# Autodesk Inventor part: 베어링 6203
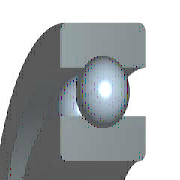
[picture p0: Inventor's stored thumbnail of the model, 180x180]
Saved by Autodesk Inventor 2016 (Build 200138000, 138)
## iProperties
IsCustomPart: 1
Created: 2015-09
Part Number: 베어링 6203
Material: 강철, 연강
Description: 깊은 그루브 볼 베어링
Document SubType Name: Modeling
Standard: KS B 2023
Standards Organization: KS
Language: ko-KR
Size Designation: 6203 - 17 x 40 x 12
Categories: <MemberInstance><Categories><Category DisplayName="샤프트 부품" InternalName="7f7aeb1f-a693-4053-b835-cee3144e0d98" Mnemonic="SHFT"><Category DisplayName="베어링" Inter
Density: 7.86 g/cm^3
Mass: 64.9809 g
Surface Area: 64.3582 cm^2
Volume: 8.26729 cm^3
Appearance: 노란색
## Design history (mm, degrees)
sketch "스케치" dims "d0" = 5.98 (= -0.26 x WD + 0.26 x BD)
  geometry: L1 (3.01, 14.25)-(8.99, 14.25); L2 (6, 14.25)-(6, 11.26); L3 (6, 14.25)-(6, 17.24); L4 (3.778, 12.249)-(0, 12.249); L5 (0, 8.5)-(12, 8.5); L6 (3.778, 16.251)-(0, 16.251); L7 (0, 20)-(12, 20); L8 (12, 8.5)-(12, 12.249); L9 (8.222, 12.249)-(12, 12.249); L10 (8.222, 16.251)-(12, 16.251); L11 (12, 20)-(12, 16.251); L12 (-1.4, 0)-(8.4, 0) reference; L13 (0, -0.3)-(0, 5.3) reference
  constraints: 22 end point, 4 point on line, 2 collinear, 2 perpendicular, 2 symmetric about line, 1 midpoint, 1 parallel, 14 other
  dimensions: "d9" = 17 diameter of L5 L12 (= WD); "d11" = 40 diameter of L7 L12 (= BD); "d12" = 12 distance between parallel lines of L8 L13 (= KB); "d13" = 24.498 diameter of L9 L12 (= 0.326 x BD + 0.674 x WD)
revolve "본체" stored, may be unused: angle "d6" = 90 deg
revolve "볼" stored, may be unused: angle "d7" = 90 deg
pattern_circular "IDS_ARRAYBALL[SIMPL:T]" dims angle "d3" = 360 deg
body "Solid1"
fillet "모깎기1" dims "d1" = 0.6 (= KRS)
other parameters: "WD" = 17 [user parameter; used in 5 equation terms], "BD" = 40 [user parameter; used in 5 equation terms], "KB" = 12 [user parameter; used in 1 equation term], "KRS" = 0.6 [user parameter; used in 1 equation term], "d4" = 0, "d5" = 0, "d8" = 0, "d14" = 0, "d15" = 0, "BBA" = 0 [user parameter], "BC0" = 4750000 [user parameter], "BC" = 9560000 [user parameter], "WR" = 8.5 (= 0.5 x WD) [user parameter]
